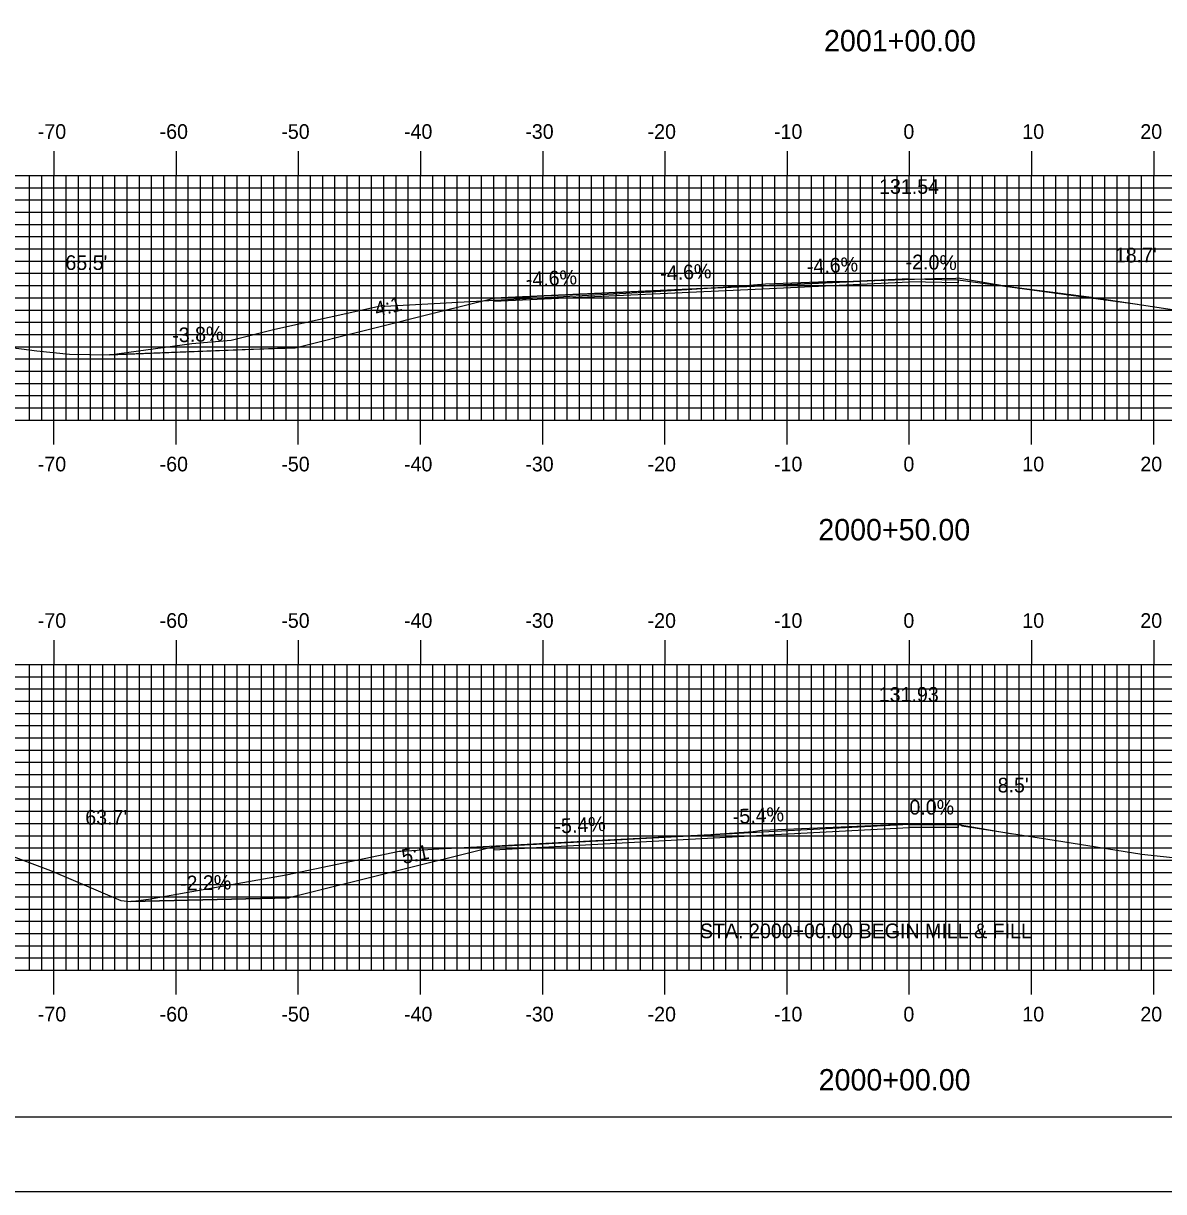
# Model space of a CAD drawing. Extents: x 850746 to 851089, y 366605 to 366825.
# Drawn here: x 850838.9 to 850932.2, y 366604.9 to 366700.5 of the extents above; entities that cross this region are included whole.
import ezdxf

# ---------------------------------------------------------------- set-up
doc = ezdxf.new("R2010")
doc.units = 0
for name, color, linetype in [('ANNOTATION', 7, 'Continuous'), ('BORDER', 7, 'Continuous'), ('D_Roadway_Centerline', 7, 'Continuous'), ('D_Roadway_Centerline_Text', 7, 'Continuous'), ('D_Roadway_Edge_Shoulder', 7, 'Continuous'), ('D_Roadway_Edge_TW', 7, 'Continuous'), ('D_Roadway_SlopeLines', 7, 'Continuous'), ('D_Text_Standard', 7, 'Continuous'), ('H_V ANNOTATION', 7, 'Continuous'), ('M_Roadway_Centerline', 7, 'Continuous'), ('MAJOR', 7, 'Continuous'), ('MINOR', 7, 'Continuous'), ('PLOT BOUNDARY', 7, 'Continuous'), ('S_Roadway_Centerline', 7, 'Continuous')]:
    doc.layers.add(name, color=color, linetype=linetype)

msp = doc.modelspace()

# ---------------------------------------------------------------- linework, layer by layer
at = {"layer": 'BORDER'}
msp.add_lwpolyline([(850761.825, 366611.055), (851081.825, 366611.055), (851081.825, 366821.055), (850761.825, 366821.055)], close=True, dxfattribs=at)
at = {"layer": 'D_Roadway_Centerline'}
for points in [[(850845.964, 366673.393), (850845.97, 366673.393), (850857.769, 366673.84), (850861.169, 366673.968), (850861.171, 366673.968), (850872.893, 366676.899), (850877.425, 366678.032), (850880.355, 366678.167), (850887.424, 366678.492), (850887.425, 366678.492), (850893.627, 366678.778), (850899.426, 366679.044), (850899.427, 366679.044), (850911.426, 366679.596), (850911.427, 366679.596), (850915.426, 366679.516), (850930.105, 366677.528)], [(850915.426, 366679.516), (850930.105, 366677.528)], [(850847.734, 366628.673), (850860.67, 366628.957)]]:
    msp.add_lwpolyline(points, dxfattribs=at)
at = {"layer": 'D_Roadway_Edge_Shoulder'}
for points in [[(850911.426, 366679.596), (850915.426, 366679.516), (850915.426, 366679.266), (850911.426, 366679.346)], [(850887.425, 366678.492), (850877.425, 366678.032), (850877.425, 366677.782), (850887.425, 366678.242)], [(850911.425, 366634.982), (850915.425, 366634.982), (850915.425, 366634.732), (850911.425, 366634.732)], [(850887.425, 366633.686), (850877.425, 366633.146), (850877.425, 366632.896), (850887.425, 366633.436)]]:
    msp.add_lwpolyline(points, close=True, dxfattribs=at)
at = {"layer": 'D_Roadway_Edge_TW'}
for points in [[(850911.426, 366679.596), (850899.425, 366679.044), (850899.425, 366678.794), (850911.426, 366679.346)], [(850899.425, 366679.044), (850887.425, 366678.492), (850887.425, 366678.242), (850899.425, 366678.794)], [(850899.426, 366634.334), (850887.425, 366633.686), (850887.425, 366633.436), (850899.426, 366634.084)], [(850911.425, 366634.982), (850899.426, 366634.334), (850899.426, 366634.084), (850911.425, 366634.732)]]:
    msp.add_lwpolyline(points, close=True, dxfattribs=at)
at = {"layer": 'D_Roadway_SlopeLines'}
msp.add_line((850915.425, 366634.982), (850919.882, 366634.208), dxfattribs=at)
for points in [[(850861.171, 366673.968), (850845.964, 366673.393)], [(850877.425, 366633.146), (850860.67, 366628.957)], [(850860.67, 366628.957), (850847.734, 366628.673)]]:
    msp.add_lwpolyline(points, dxfattribs=at)
at = {"layer": 'MAJOR'}
for p, q in [((850841.425, 366690.059), (850841.425, 366688.055)), ((850851.425, 366690.059), (850851.425, 366688.055)), ((850861.425, 366690.059), (850861.425, 366688.055)), ((850871.425, 366690.059), (850871.425, 366688.055)), ((850881.425, 366690.059), (850881.425, 366688.055)), ((850891.425, 366690.059), (850891.425, 366688.055)), ((850901.425, 366690.059), (850901.425, 366688.055)), ((850911.425, 366690.059), (850911.425, 366688.055)), ((850921.425, 366690.059), (850921.425, 366688.055)), ((850931.425, 366690.059), (850931.425, 366688.055)), ((850771.425, 366688.055), (851051.425, 366688.055)), ((850771.425, 366688.055), (851051.425, 366688.055)), ((850841.425, 366668.055), (850841.425, 366688.055)), ((850851.425, 366668.055), (850851.425, 366688.055)), ((850861.425, 366668.055), (850861.425, 366688.055)), ((850871.425, 366668.055), (850871.425, 366688.055)), ((850881.425, 366668.055), (850881.425, 366688.055)), ((850891.425, 366668.055), (850891.425, 366688.055)), ((850901.425, 366668.055), (850901.425, 366688.055)), ((850911.425, 366668.055), (850911.425, 366688.055)), ((850921.425, 366668.055), (850921.425, 366688.055)), ((850931.425, 366668.055), (850931.425, 366688.055)), ((850771.425, 366683.055), (851051.425, 366683.055)), ((850771.425, 366678.055), (851051.425, 366678.055)), ((850771.425, 366673.055), (851051.425, 366673.055)), ((850771.425, 366668.055), (851051.425, 366668.055)), ((850771.425, 366668.055), (851051.425, 366668.055)), ((850841.425, 366666.051), (850841.425, 366668.055)), ((850851.425, 366666.051), (850851.425, 366668.055)), ((850861.425, 366666.051), (850861.425, 366668.055)), ((850871.425, 366666.051), (850871.425, 366668.055)), ((850881.425, 366666.051), (850881.425, 366668.055)), ((850891.425, 366666.051), (850891.425, 366668.055)), ((850901.425, 366666.051), (850901.425, 366668.055)), ((850911.425, 366666.051), (850911.425, 366668.055)), ((850921.425, 366666.051), (850921.425, 366668.055)), ((850931.425, 366666.051), (850931.425, 366668.055)), ((850841.425, 366650.059), (850841.425, 366648.055)), ((850851.425, 366650.059), (850851.425, 366648.055)), ((850861.425, 366650.059), (850861.425, 366648.055)), ((850871.425, 366650.059), (850871.425, 366648.055)), ((850881.425, 366650.059), (850881.425, 366648.055)), ((850891.425, 366650.059), (850891.425, 366648.055)), ((850901.425, 366650.059), (850901.425, 366648.055)), ((850911.425, 366650.059), (850911.425, 366648.055)), ((850921.425, 366650.059), (850921.425, 366648.055)), ((850931.425, 366650.059), (850931.425, 366648.055)), ((850771.425, 366648.055), (851051.425, 366648.055)), ((850771.425, 366648.055), (851051.425, 366648.055)), ((850841.425, 366623.055), (850841.425, 366648.055)), ((850851.425, 366623.055), (850851.425, 366648.055)), ((850861.425, 366623.055), (850861.425, 366648.055)), ((850871.425, 366623.055), (850871.425, 366648.055)), ((850881.425, 366623.055), (850881.425, 366648.055)), ((850891.425, 366623.055), (850891.425, 366648.055)), ((850901.425, 366623.055), (850901.425, 366648.055)), ((850911.425, 366623.055), (850911.425, 366648.055)), ((850921.425, 366623.055), (850921.425, 366648.055)), ((850931.425, 366623.055), (850931.425, 366648.055)), ((850771.425, 366643.055), (851051.425, 366643.055)), ((850771.425, 366638.055), (851051.425, 366638.055)), ((850771.425, 366633.055), (851051.425, 366633.055)), ((850771.425, 366628.055), (851051.425, 366628.055)), ((850771.425, 366623.055), (851051.425, 366623.055)), ((850771.425, 366623.055), (851051.425, 366623.055)), ((850841.425, 366621.051), (850841.425, 366623.055)), ((850851.425, 366621.051), (850851.425, 366623.055)), ((850861.425, 366621.051), (850861.425, 366623.055)), ((850871.425, 366621.051), (850871.425, 366623.055)), ((850881.425, 366621.051), (850881.425, 366623.055)), ((850891.425, 366621.051), (850891.425, 366623.055)), ((850901.425, 366621.051), (850901.425, 366623.055)), ((850911.425, 366621.051), (850911.425, 366623.055)), ((850921.425, 366621.051), (850921.425, 366623.055)), ((850931.425, 366621.051), (850931.425, 366623.055))]:
    msp.add_line(p, q, dxfattribs=at)
at = {"layer": 'MINOR'}
for p, q in [((850839.425, 366668.055), (850839.425, 366688.055)), ((850840.425, 366668.055), (850840.425, 366688.055)), ((850842.425, 366668.055), (850842.425, 366688.055)), ((850843.425, 366668.055), (850843.425, 366688.055)), ((850844.425, 366668.055), (850844.425, 366688.055)), ((850845.425, 366668.055), (850845.425, 366688.055)), ((850846.425, 366668.055), (850846.425, 366688.055)), ((850847.425, 366668.055), (850847.425, 366688.055)), ((850848.425, 366668.055), (850848.425, 366688.055)), ((850849.425, 366668.055), (850849.425, 366688.055)), ((850850.425, 366668.055), (850850.425, 366688.055)), ((850852.425, 366668.055), (850852.425, 366688.055)), ((850853.425, 366668.055), (850853.425, 366688.055)), ((850854.425, 366668.055), (850854.425, 366688.055)), ((850855.425, 366668.055), (850855.425, 366688.055)), ((850856.425, 366668.055), (850856.425, 366688.055)), ((850857.425, 366668.055), (850857.425, 366688.055)), ((850858.425, 366668.055), (850858.425, 366688.055)), ((850859.425, 366668.055), (850859.425, 366688.055)), ((850860.425, 366668.055), (850860.425, 366688.055)), ((850862.425, 366668.055), (850862.425, 366688.055)), ((850863.425, 366668.055), (850863.425, 366688.055)), ((850864.425, 366668.055), (850864.425, 366688.055)), ((850865.425, 366668.055), (850865.425, 366688.055)), ((850866.425, 366668.055), (850866.425, 366688.055)), ((850867.425, 366668.055), (850867.425, 366688.055)), ((850868.425, 366668.055), (850868.425, 366688.055)), ((850869.425, 366668.055), (850869.425, 366688.055)), ((850870.425, 366668.055), (850870.425, 366688.055)), ((850872.425, 366668.055), (850872.425, 366688.055)), ((850873.425, 366668.055), (850873.425, 366688.055)), ((850874.425, 366668.055), (850874.425, 366688.055)), ((850875.425, 366668.055), (850875.425, 366688.055)), ((850876.425, 366668.055), (850876.425, 366688.055)), ((850877.425, 366668.055), (850877.425, 366688.055)), ((850878.425, 366668.055), (850878.425, 366688.055)), ((850879.425, 366668.055), (850879.425, 366688.055)), ((850880.425, 366668.055), (850880.425, 366688.055)), ((850882.425, 366668.055), (850882.425, 366688.055)), ((850883.425, 366668.055), (850883.425, 366688.055)), ((850884.425, 366668.055), (850884.425, 366688.055)), ((850885.425, 366668.055), (850885.425, 366688.055)), ((850886.425, 366668.055), (850886.425, 366688.055)), ((850887.425, 366668.055), (850887.425, 366688.055)), ((850888.425, 366668.055), (850888.425, 366688.055)), ((850889.425, 366668.055), (850889.425, 366688.055)), ((850890.425, 366668.055), (850890.425, 366688.055)), ((850892.425, 366668.055), (850892.425, 366688.055)), ((850893.425, 366668.055), (850893.425, 366688.055)), ((850894.425, 366668.055), (850894.425, 366688.055)), ((850895.425, 366668.055), (850895.425, 366688.055)), ((850896.425, 366668.055), (850896.425, 366688.055)), ((850897.425, 366668.055), (850897.425, 366688.055)), ((850898.425, 366668.055), (850898.425, 366688.055)), ((850899.425, 366668.055), (850899.425, 366688.055)), ((850900.425, 366668.055), (850900.425, 366688.055)), ((850902.425, 366668.055), (850902.425, 366688.055)), ((850903.425, 366668.055), (850903.425, 366688.055)), ((850904.425, 366668.055), (850904.425, 366688.055)), ((850905.425, 366668.055), (850905.425, 366688.055)), ((850906.425, 366668.055), (850906.425, 366688.055)), ((850907.425, 366668.055), (850907.425, 366688.055)), ((850908.425, 366668.055), (850908.425, 366688.055)), ((850909.425, 366668.055), (850909.425, 366688.055)), ((850910.425, 366668.055), (850910.425, 366688.055)), ((850912.425, 366668.055), (850912.425, 366688.055)), ((850913.425, 366668.055), (850913.425, 366688.055)), ((850914.425, 366668.055), (850914.425, 366688.055)), ((850915.425, 366668.055), (850915.425, 366688.055)), ((850916.425, 366668.055), (850916.425, 366688.055)), ((850917.425, 366668.055), (850917.425, 366688.055)), ((850918.425, 366668.055), (850918.425, 366688.055)), ((850919.425, 366668.055), (850919.425, 366688.055)), ((850920.425, 366668.055), (850920.425, 366688.055)), ((850922.425, 366668.055), (850922.425, 366688.055)), ((850923.425, 366668.055), (850923.425, 366688.055)), ((850924.425, 366668.055), (850924.425, 366688.055)), ((850925.425, 366668.055), (850925.425, 366688.055)), ((850926.425, 366668.055), (850926.425, 366688.055)), ((850927.425, 366668.055), (850927.425, 366688.055)), ((850928.425, 366668.055), (850928.425, 366688.055)), ((850929.425, 366668.055), (850929.425, 366688.055)), ((850930.425, 366668.055), (850930.425, 366688.055)), ((850771.425, 366687.055), (851051.425, 366687.055)), ((850771.425, 366686.055), (851051.425, 366686.055)), ((850771.425, 366685.055), (851051.425, 366685.055)), ((850771.425, 366684.055), (851051.425, 366684.055)), ((850771.425, 366682.055), (851051.425, 366682.055)), ((850771.425, 366681.055), (851051.425, 366681.055)), ((850771.425, 366680.055), (851051.425, 366680.055)), ((850771.425, 366679.055), (851051.425, 366679.055)), ((850771.425, 366677.055), (851051.425, 366677.055)), ((850771.425, 366676.055), (851051.425, 366676.055)), ((850771.425, 366675.055), (851051.425, 366675.055)), ((850771.425, 366674.055), (851051.425, 366674.055)), ((850771.425, 366672.055), (851051.425, 366672.055)), ((850771.425, 366671.055), (851051.425, 366671.055)), ((850771.425, 366670.055), (851051.425, 366670.055)), ((850771.425, 366669.055), (851051.425, 366669.055)), ((850839.425, 366623.055), (850839.425, 366648.055)), ((850840.425, 366623.055), (850840.425, 366648.055)), ((850842.425, 366623.055), (850842.425, 366648.055)), ((850843.425, 366623.055), (850843.425, 366648.055)), ((850844.425, 366623.055), (850844.425, 366648.055)), ((850845.425, 366623.055), (850845.425, 366648.055)), ((850846.425, 366623.055), (850846.425, 366648.055)), ((850847.425, 366623.055), (850847.425, 366648.055)), ((850848.425, 366623.055), (850848.425, 366648.055)), ((850849.425, 366623.055), (850849.425, 366648.055)), ((850850.425, 366623.055), (850850.425, 366648.055)), ((850852.425, 366623.055), (850852.425, 366648.055)), ((850853.425, 366623.055), (850853.425, 366648.055)), ((850854.425, 366623.055), (850854.425, 366648.055)), ((850855.425, 366623.055), (850855.425, 366648.055)), ((850856.425, 366623.055), (850856.425, 366648.055)), ((850857.425, 366623.055), (850857.425, 366648.055)), ((850858.425, 366623.055), (850858.425, 366648.055)), ((850859.425, 366623.055), (850859.425, 366648.055)), ((850860.425, 366623.055), (850860.425, 366648.055)), ((850862.425, 366623.055), (850862.425, 366648.055)), ((850863.425, 366623.055), (850863.425, 366648.055)), ((850864.425, 366623.055), (850864.425, 366648.055)), ((850865.425, 366623.055), (850865.425, 366648.055)), ((850866.425, 366623.055), (850866.425, 366648.055)), ((850867.425, 366623.055), (850867.425, 366648.055)), ((850868.425, 366623.055), (850868.425, 366648.055)), ((850869.425, 366623.055), (850869.425, 366648.055)), ((850870.425, 366623.055), (850870.425, 366648.055)), ((850872.425, 366623.055), (850872.425, 366648.055)), ((850873.425, 366623.055), (850873.425, 366648.055)), ((850874.425, 366623.055), (850874.425, 366648.055)), ((850875.425, 366623.055), (850875.425, 366648.055)), ((850876.425, 366623.055), (850876.425, 366648.055)), ((850877.425, 366623.055), (850877.425, 366648.055)), ((850878.425, 366623.055), (850878.425, 366648.055)), ((850879.425, 366623.055), (850879.425, 366648.055)), ((850880.425, 366623.055), (850880.425, 366648.055)), ((850882.425, 366623.055), (850882.425, 366648.055)), ((850883.425, 366623.055), (850883.425, 366648.055)), ((850884.425, 366623.055), (850884.425, 366648.055)), ((850885.425, 366623.055), (850885.425, 366648.055)), ((850886.425, 366623.055), (850886.425, 366648.055)), ((850887.425, 366623.055), (850887.425, 366648.055)), ((850888.425, 366623.055), (850888.425, 366648.055)), ((850889.425, 366623.055), (850889.425, 366648.055)), ((850890.425, 366623.055), (850890.425, 366648.055)), ((850892.425, 366623.055), (850892.425, 366648.055)), ((850893.425, 366623.055), (850893.425, 366648.055)), ((850894.425, 366623.055), (850894.425, 366648.055)), ((850895.425, 366623.055), (850895.425, 366648.055)), ((850896.425, 366623.055), (850896.425, 366648.055)), ((850897.425, 366623.055), (850897.425, 366648.055)), ((850898.425, 366623.055), (850898.425, 366648.055)), ((850899.425, 366623.055), (850899.425, 366648.055)), ((850900.425, 366623.055), (850900.425, 366648.055)), ((850902.425, 366623.055), (850902.425, 366648.055)), ((850903.425, 366623.055), (850903.425, 366648.055)), ((850904.425, 366623.055), (850904.425, 366648.055)), ((850905.425, 366623.055), (850905.425, 366648.055)), ((850906.425, 366623.055), (850906.425, 366648.055)), ((850907.425, 366623.055), (850907.425, 366648.055)), ((850908.425, 366623.055), (850908.425, 366648.055)), ((850909.425, 366623.055), (850909.425, 366648.055)), ((850910.425, 366623.055), (850910.425, 366648.055)), ((850912.425, 366623.055), (850912.425, 366648.055)), ((850913.425, 366623.055), (850913.425, 366648.055)), ((850914.425, 366623.055), (850914.425, 366648.055)), ((850915.425, 366623.055), (850915.425, 366648.055)), ((850916.425, 366623.055), (850916.425, 366648.055)), ((850917.425, 366623.055), (850917.425, 366648.055)), ((850918.425, 366623.055), (850918.425, 366648.055)), ((850919.425, 366623.055), (850919.425, 366648.055)), ((850920.425, 366623.055), (850920.425, 366648.055)), ((850922.425, 366623.055), (850922.425, 366648.055)), ((850923.425, 366623.055), (850923.425, 366648.055)), ((850924.425, 366623.055), (850924.425, 366648.055)), ((850925.425, 366623.055), (850925.425, 366648.055)), ((850926.425, 366623.055), (850926.425, 366648.055)), ((850927.425, 366623.055), (850927.425, 366648.055)), ((850928.425, 366623.055), (850928.425, 366648.055)), ((850929.425, 366623.055), (850929.425, 366648.055)), ((850930.425, 366623.055), (850930.425, 366648.055)), ((850771.425, 366647.055), (851051.425, 366647.055)), ((850771.425, 366646.055), (851051.425, 366646.055)), ((850771.425, 366645.055), (851051.425, 366645.055)), ((850771.425, 366644.055), (851051.425, 366644.055)), ((850771.425, 366642.055), (851051.425, 366642.055)), ((850771.425, 366641.055), (851051.425, 366641.055)), ((850771.425, 366640.055), (851051.425, 366640.055)), ((850771.425, 366639.055), (851051.425, 366639.055)), ((850771.425, 366637.055), (851051.425, 366637.055)), ((850771.425, 366636.055), (851051.425, 366636.055)), ((850771.425, 366635.055), (851051.425, 366635.055)), ((850771.425, 366634.055), (851051.425, 366634.055)), ((850771.425, 366632.055), (851051.425, 366632.055)), ((850771.425, 366631.055), (851051.425, 366631.055)), ((850771.425, 366630.055), (851051.425, 366630.055)), ((850771.425, 366629.055), (851051.425, 366629.055)), ((850771.425, 366627.055), (851051.425, 366627.055)), ((850771.425, 366626.055), (851051.425, 366626.055)), ((850771.425, 366625.055), (851051.425, 366625.055)), ((850771.425, 366624.055), (851051.425, 366624.055))]:
    msp.add_line(p, q, dxfattribs=at)
at = {"layer": 'PLOT BOUNDARY'}
msp.add_lwpolyline([(850745.639, 366604.937), (851085.639, 366604.937), (851085.639, 366824.937), (850745.639, 366824.937)], close=True, dxfattribs=at)
at = {"layer": 'S_Roadway_Centerline'}
for points in [[(850834.55, 366674.417), (850840.022, 366673.714), (850842.705, 366673.449), (850845.963, 366673.394), (850852.713, 366674.317), (850855.931, 366674.584), (850859.518, 366675.498), (850868.408, 366677.456), (850868.504, 366677.378), (850873.039, 366677.622), (850874.479, 366677.709), (850880.077, 366678.002), (850888.233, 366678.432), (850890.239, 366678.535), (850897.048, 366678.986), (850899.67, 366679.189), (850904.717, 366679.385), (850906.959, 366679.417), (850913.478, 366679.641), (850915.222, 366679.656), (850915.411, 366679.674), (850919.561, 366678.977), (850926.126, 366678.137), (850940.861, 366675.883)], [(850829.346, 366635.618), (850841.149, 366631.205), (850846.914, 366628.76), (850847.734, 366628.673), (850849.157, 366628.861), (850860.42, 366630.85), (850869.168, 366632.674), (850869.688, 366632.792), (850869.812, 366632.799), (850872.918, 366632.966), (850878.106, 366633.246), (850891.384, 366633.955), (850895.187, 366634.158), (850898.639, 366634.404), (850899.397, 366634.516), (850909.734, 366634.937), (850912.52, 366635.011), (850915.602, 366634.998), (850915.762, 366634.849), (850924.002, 366633.568), (850930.466, 366632.554), (850938.503, 366631.665)]]:
    msp.add_lwpolyline(points, dxfattribs=at)

# ---------------------------------------------------------------- texts
at = {"layer": 'ANNOTATION'}
for s, rotation, p in [('-4.6%', 2.6337, (850903.068, 366680.014)), ('-2.0%', 358.85467, (850911.113, 366680.403)), ('-4.6%', 2.63368, (850880.067, 366678.956)), ('-4.6%', 2.6337, (850891.067, 366679.462)), ('4:1', 14.03784, (850867.834, 366676.496)), ('-3.8%', 2.16538, (850851.131, 366674.39)), ('-5.4%', 3.09101, (850897.012, 366635.007)), ('0.0%', 0.00004, (850911.435, 366635.782)), ('-5.4%', 3.09087, (850882.418, 366634.219)), ('5:1', 11.65106, (850870.024, 366631.728)), ('-2.2%', 1.25767, (850851.761, 366629.562))]:
    msp.add_text(s, height=1.2, rotation=rotation, dxfattribs=at).set_placement(p)
msp.add_text('STA. 2000+00.00 BEGIN MILL & FILL', height=1.2, dxfattribs=at).set_placement((850894.294, 366625.667))
at = {"layer": 'D_Roadway_Centerline_Text'}
for s, p in [('131.54', (850908.953, 366686.557)), ('131.93', (850908.927, 366645.012))]:
    msp.add_text(s, height=1.2, dxfattribs=at).set_placement(p)
at = {"layer": 'D_Text_Standard'}
for s, p in [("18.7'", (850928.248, 366680.949)), ("65.5'", (850842.366, 366680.331)), ("8.5'", (850918.657, 366637.591)), ("63.7'", (850843.991, 366634.955))]:
    msp.add_text(s, height=1.2, dxfattribs=at).set_placement(p)
at = {"layer": 'H_V ANNOTATION'}
for s, height, p in [('2001+00.00', 1.75, (850904.449, 366698.211)), ('-70', 1.2, (850840.109, 366691.055)), ('-60', 1.2, (850850.077, 366691.055)), ('-50', 1.2, (850860.034, 366691.055)), ('-40', 1.2, (850870.077, 366691.055)), ('-30', 1.2, (850880.002, 366691.055)), ('-20', 1.2, (850890.012, 366691.055)), ('-10', 1.2, (850900.355, 366691.055)), ('0', 1.2, (850910.943, 366691.055)), ('10', 1.2, (850920.676, 366691.055)), ('20', 1.2, (850930.333, 366691.055)), ('-70', 1.2, (850840.109, 366663.855)), ('-60', 1.2, (850850.077, 366663.855)), ('-50', 1.2, (850860.034, 366663.855)), ('-40', 1.2, (850870.077, 366663.855)), ('-30', 1.2, (850880.002, 366663.855)), ('-20', 1.2, (850890.012, 366663.855)), ('-10', 1.2, (850900.355, 366663.855)), ('0', 1.2, (850910.943, 366663.855)), ('10', 1.2, (850920.676, 366663.855)), ('20', 1.2, (850930.333, 366663.855)), ('2000+50.00', 1.75, (850903.981, 366658.211)), ('-70', 1.2, (850840.109, 366651.055)), ('-60', 1.2, (850850.077, 366651.055)), ('-50', 1.2, (850860.034, 366651.055)), ('-40', 1.2, (850870.077, 366651.055)), ('-30', 1.2, (850880.002, 366651.055)), ('-20', 1.2, (850890.012, 366651.055)), ('-10', 1.2, (850900.355, 366651.055)), ('0', 1.2, (850910.943, 366651.055)), ('10', 1.2, (850920.676, 366651.055)), ('20', 1.2, (850930.333, 366651.055)), ('-70', 1.2, (850840.109, 366618.855)), ('-60', 1.2, (850850.077, 366618.855)), ('-50', 1.2, (850860.034, 366618.855)), ('-40', 1.2, (850870.077, 366618.855)), ('-30', 1.2, (850880.002, 366618.855)), ('-20', 1.2, (850890.012, 366618.855)), ('-10', 1.2, (850900.355, 366618.855)), ('0', 1.2, (850910.943, 366618.855)), ('10', 1.2, (850920.676, 366618.855)), ('20', 1.2, (850930.333, 366618.855)), ('2000+00.00', 1.75, (850904.012, 366613.211))]:
    msp.add_text(s, height=height, dxfattribs=at).set_placement(p)
at = {"layer": 'M_Roadway_Centerline'}
for s, p in [('C', (850899.665, 366679.189)), ('L', (850899.67, 366679.181)), ('C', (850899.392, 366634.516)), ('L', (850899.397, 366634.509))]:
    msp.add_text(s, height=0.0146, dxfattribs=at).set_placement(p)

doc.saveas('drawing.dxf')
